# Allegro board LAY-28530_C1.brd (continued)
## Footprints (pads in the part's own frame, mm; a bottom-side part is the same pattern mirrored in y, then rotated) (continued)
FUSE_HOLD_10P4X3_TH
  rect 1.905x1.905 hole 1.295: 1(0,0)
  round 1.905 hole 1.295: 2(5.1,-1.199)
HDR1X3_50MIL
  rect 1.092x1.092 hole 0.711: 1(0,0)
  round 1.092 hole 0.711: 2(0,-1.27) 3(0,-2.54)
HDR2X4_50MIL
  rect 1.092x1.092 hole 0.711: 1(0,0)
  round 1.092 hole 0.711: 2(1.27,0) 3(0,-1.27) 4(1.27,-1.27) 5(0,-2.54) 6(1.27,-2.54) 7(0,-3.81) 8(1.27,-3.81)
HDR102
  rect 1.524x1.524 hole 1.016: 1(0,0)
  round 1.524 hole 1.016: 2(0,-2.54)
HDR103
  rect 1.524x1.524 hole 1.016: 1(0,0)
  round 1.524 hole 1.016: 2(0,-2.54) 3(0,-5.08)
HDR208_HTST_SM
  rect 5.08x1.27 smd: 1(-3.429,8.89) 2(3.429,8.89) 3(-3.429,6.35) 4(3.429,6.35) 5(-3.429,3.81) 6(3.429,3.81) 7(-3.429,1.27) 8(3.429,1.27) 9(-3.429,-1.27) 10(3.429,-1.27) 11(-3.429,-3.81) 12(3.429,-3.81) 13(-3.429,-6.35) 14(3.429,-6.35) 15(-3.429,-8.89) 16(3.429,-8.89)
IND2_4P3SQ_XFL4020
  rect 0.965x3.404 smd: 1(-1.186,0) 2(1.186,0)
IND2_4P3X4P3
  rect 1.118x3.708 smd: 1(-1.501,0) 2(1.501,0)
IND2_XAL40
  rect 0.965x3.708 smd: 1(-1.186,0) 2(1.186,0)
IND2_XAL50XX_222
  rect 1.168x4.394 smd: 1(-1.651,0) 2(1.651,0)
IND4_CHOKE_0805
  rect 0.914x0.406 smd: 1(-0.851,-0.399) 2(0.851,-0.399) 3(0.851,0.399) 4(-0.851,0.399)
IND_0402
  round 0.635 smd: 1(-0.508,0) 2(0.508,0)
IND_0603
  rect 0.991x0.813 smd: 1(-0.691,0) 2(0.691,0)
IND_0805
  rect 1.295x1.499 smd: 1(-0.978,0) 2(0.978,0)
IND_DO1608
  rect 1.397x3.556 smd: 1(-2.743,0) 2(2.743,0)
IND_DO1813
  rect 1.905x4.089 smd: 1(-3.487,0) 2(3.487,0)
IND_DS3316
  rect 2.997x2.794 smd: 1(-5.08,0) 2(5.08,0)
JUMP1X7-6040
  rect 1.524x1.524 hole 1.016: 1(0,0)
  round 1.524 hole 1.016: 2(0,-2.54) 3(0,-5.08) 4(0,-7.62) 5(0,-10.16) 6(0,-12.7) 7(0,-15.24)
LED2_2P54_6P6X4P3MM
  round 1.676 hole 1.067: A(0,2.54)
  rect 1.676x1.676 hole 1.067: C(0,0)
LED4_2P54_9P3X4P5MM
  rect 1.727x1.727 hole 1.092: 1(0,0)
  round 1.727 hole 1.092: 2(-2.54,0) 3(0,-2.54) 4(-2.54,-2.54)
LED_0603
  rect 0.838x0.787 smd: A(-0.775,0) C(0.775,0)
MH175-125P
  round 4.445 hole 3.175: 1(0,0)
MSOP_10_0P5_3X3
  rect 1.372x0.279 smd: 1(-2.24,1.001) 2(-2.24,0.5) 3(-2.24,0) 4(-2.24,-0.5) 5(-2.24,-1.001) 6(2.24,-1.001) 7(2.24,-0.5) 8(2.24,0) 9(2.24,0.5) 10(2.24,1.001)
PQFN16_0P4_2P65X1P85
  rect 0.203x0.762 smd: 1(-0.599,-0.724)
  rect 0.203x0.66 smd: 2(-0.201,-0.775) 3(0.201,-0.775) 4(0.599,-0.775) 9(0.599,0.775) 10(0.201,0.775) 11(-0.201,0.775) 12(-0.599,0.775)
  rect 0.66x0.203 smd: 5(1.209,-0.599) 6(1.209,-0.201) 7(1.209,0.201) 8(1.209,0.599) 13(-1.209,0.599) 14(-1.209,0.201) 15(-1.209,-0.201) 16(-1.209,-0.599)
QFN24_0P5_4X4_EP2P2
  oval 0.813x0.279 smd: 1(-1.859,1.25) 2(-1.859,0.749) 3(-1.859,0.249) 4(-1.859,-0.249) 5(-1.859,-0.749) 6(-1.859,-1.25) 13(1.859,-1.25) 14(1.859,-0.749) 15(1.859,-0.249) 16(1.859,0.249) 17(1.859,0.749) 18(1.859,1.25)
  oval 0.279x0.813 smd: 7(-1.25,-1.859) 8(-0.749,-1.859) 9(-0.249,-1.859) 10(0.249,-1.859) 11(0.749,-1.859) 12(1.25,-1.859) 19(1.25,1.859) 20(0.749,1.859) 21(0.249,1.859) 22(-0.249,1.859) 23(-0.749,1.859) 24(-1.25,1.859)
  rect 2.438x2.438 smd: 25(0,0)
QFN24_4X4MM
  rect 0.279x0.787 smd: 1(-1.25,-1.956) 2(-0.749,-1.956) 3(-0.249,-1.956) 4(0.249,-1.956) 5(0.749,-1.956) 6(1.25,-1.956) 13(1.25,1.956) 14(0.749,1.956) 15(0.249,1.956) 16(-0.249,1.956) 17(-0.749,1.956) 18(-1.25,1.956)
  rect 0.787x0.279 smd: 7(1.956,-1.25) 8(1.956,-0.749) 9(1.956,-0.249) 10(1.956,0.249) 11(1.956,0.749) 12(1.956,1.25) 19(-1.956,1.25) 20(-1.956,0.749) 21(-1.956,0.249) 22(-1.956,-0.249) 23(-1.956,-0.749) 24(-1.956,-1.25)
  rect 2.515x2.515 smd: 25(0,0)
QFN28_3X6_0P5
  rect 0.686x0.254 smd: 1(-1.493,2.25) 2(-1.493,1.75) 3(-1.493,1.25) 4(-1.493,0.749) 5(-1.493,0.249) 6(-1.493,-0.249) 7(-1.493,-0.749) 8(-1.493,-1.25) 9(-1.493,-1.75) 10(-1.493,-2.25) 15(1.493,-2.25) 16(1.493,-1.75) 17(1.493,-1.25) 18(1.493,-0.749) 19(1.493,-0.249) 20(1.493,0.249) 21(1.493,0.749) 22(1.493,1.25) 23(1.493,1.75) 24(1.493,2.25)
  rect 0.254x0.686 smd: 11(-0.749,-2.992) 12(-0.249,-2.992) 13(0.249,-2.992) 14(0.749,-2.992) 25(0.749,2.992) 26(0.249,2.992) 27(-0.249,2.992) 28(-0.749,2.992)
  rect 1.702x4.75 smd: 29(0,0)
QFN56_0P5_8X8_EP4P1X4P4
  oval 0.838x0.279 smd: 1(-3.97,3.251) 14(-3.97,-3.251) 29(3.97,-3.251) 42(3.97,3.251)
  rect 0.838x0.279 smd: 2(-3.97,2.751) 3(-3.97,2.25) 4(-3.97,1.75) 5(-3.97,1.25) 6(-3.97,0.749) 7(-3.97,0.249) 8(-3.97,-0.249) 9(-3.97,-0.749) 10(-3.97,-1.25) 11(-3.97,-1.75) 12(-3.97,-2.25) 13(-3.97,-2.751) 30(3.97,-2.751) 31(3.97,-2.25) 32(3.97,-1.75) 33(3.97,-1.25) 34(3.97,-0.749) 35(3.97,-0.249) 36(3.97,0.249) 37(3.97,0.749) 38(3.97,1.25) 39(3.97,1.75) 40(3.97,2.25) 41(3.97,2.751)
  oval 0.279x0.838 smd: 15(-3.251,-3.97) 28(3.251,-3.97) 43(3.251,3.97) 56(-3.251,3.97)
  rect 0.279x0.838 smd: 16(-2.751,-3.97) 17(-2.25,-3.97) 18(-1.75,-3.97) 19(-1.25,-3.97) 20(-0.749,-3.97) 21(-0.249,-3.97) 22(0.249,-3.97) 23(0.749,-3.97) 24(1.25,-3.97) 25(1.75,-3.97) 26(2.25,-3.97) 27(2.751,-3.97) 44(2.751,3.97) 45(2.25,3.97) 46(1.75,3.97) 47(1.25,3.97) 48(0.749,3.97) 49(0.249,3.97) 50(-0.249,3.97) 51(-0.749,3.97) 52(-1.25,3.97) 53(-1.75,3.97) 54(-2.25,3.97) 55(-2.751,3.97)
  rect 4.115x4.42 smd: 57(0,0)
QFN_48_0P4_6X6MM
  rect 0.838x0.203 smd: 1(-2.936,2.2) 2(-2.936,1.801) 3(-2.936,1.399) 4(-2.936,1.001) 5(-2.936,0.599) 6(-2.936,0.201) 7(-2.936,-0.201) 8(-2.936,-0.599) 9(-2.936,-1.001) 10(-2.936,-1.399) 11(-2.936,-1.801) 12(-2.936,-2.2) 25(2.936,-2.2) 26(2.936,-1.801) 27(2.936,-1.399) 28(2.936,-1.001) 29(2.936,-0.599) 30(2.936,-0.201) 31(2.936,0.201) 32(2.936,0.599) 33(2.936,1.001) 34(2.936,1.399) 35(2.936,1.801) 36(2.936,2.2)
  rect 0.203x0.838 smd: 13(-2.2,-2.936) 14(-1.801,-2.936) 15(-1.399,-2.936) 16(-1.001,-2.936) 17(-0.599,-2.936) 18(-0.201,-2.936) 19(0.201,-2.936) 20(0.599,-2.936) 21(1.001,-2.936) 22(1.399,-2.936) 23(1.801,-2.936) 24(2.2,-2.936) 37(2.2,2.936) 38(1.801,2.936) 39(1.399,2.936) 40(1.001,2.936) 41(0.599,2.936) 42(0.201,2.936) 43(-0.201,2.936) 44(-0.599,2.936) 45(-1.001,2.936) 46(-1.399,2.936) 47(-1.801,2.936) 48(-2.2,2.936)
  rect 4.597x4.597 smd: 49(0,0)
RC0402_25
  round 0.635 smd: 1(-0.508,0) 2(0.508,0)
RC0603_OV
  oval 0.889x1.143 smd: 1(-0.762,0) 2(0.762,0)
RC0805_OV
  oval 0.889x1.524 smd: 1(-0.965,0) 2(0.965,0)
RC1206_OV
  oval 1.016x1.778 smd: 1(-1.524,0) 2(1.524,0)
SKT_BAT_225X886_3V
  rect 1.651x1.651 hole 1.016: 1(0,0)
  round 1.651 hole 1.016: 2(10,0) 3(5.001,3.47)
SKT_BGA525_0P8_58P6SQ_SM
  round 0.254 hole 3.708 unplated: (-24.13,24.13) (-24.13,-24.13) (24.13,24.13) (24.13,-24.13)
  round 0.254 hole 2.438 unplated: (-19.05,24.13) (24.13,-19.05)
  round 0.381 smd: A2(-8.001,8.801) A3(-7.201,8.801) A4(-6.401,8.801) A5(-5.601,8.801) A6(-4.801,8.801) A7(-4,8.801) A8(-3.2,8.801) A9(-2.4,8.801) A10(-1.6,8.801) A11(-0.8,8.801) A12(0,8.801) A13(0.8,8.801) A14(1.6,8.801) A15(2.4,8.801) A16(3.2,8.801) A17(4,8.801) A18(4.801,8.801) A19(5.601,8.801) A20(6.401,8.801) A21(7.201,8.801) A22(8.001,8.801) AA1(-8.801,-7.201) AA2(-8.001,-7.201) AA3(-7.201,-7.201) AA4(-6.401,-7.201) AA5(-5.601,-7.201) AA6(-4.801,-7.201) AA7(-4,-7.201) AA8(-3.2,-7.201) AA9(-2.4,-7.201) AA10(-1.6,-7.201) AA11(-0.8,-7.201) AA12(0,-7.201) AA13(0.8,-7.201) AA14(1.6,-7.201) AA15(2.4,-7.201) AA16(3.2,-7.201) AA17(4,-7.201) AA18(4.801,-7.201) AA19(5.601,-7.201) AA20(6.401,-7.201) AA21(7.201,-7.201) AA22(8.001,-7.201) AA23(8.801,-7.201) AB1(-8.801,-8.001) AB2(-8.001,-8.001) AB3(-7.201,-8.001) AB4(-6.401,-8.001) AB5(-5.601,-8.001) AB6(-4.801,-8.001) AB7(-4,-8.001) AB8(-3.2,-8.001) AB9(-2.4,-8.001) AB10(-1.6,-8.001) AB11(-0.8,-8.001) AB12(0,-8.001) AB13(0.8,-8.001) AB14(1.6,-8.001) AB15(2.4,-8.001) AB16(3.2,-8.001) AB17(4,-8.001) AB18(4.801,-8.001) AB19(5.601,-8.001) AB20(6.401,-8.001) AB21(7.201,-8.001) AB22(8.001,-8.001) AB23(8.801,-8.001) AC2(-8.001,-8.801) AC3(-7.201,-8.801) AC4(-6.401,-8.801) AC5(-5.601,-8.801) AC6(-4.801,-8.801) AC7(-4,-8.801) AC8(-3.2,-8.801) AC9(-2.4,-8.801) AC10(-1.6,-8.801) AC11(-0.8,-8.801) AC12(0,-8.801) AC13(0.8,-8.801) AC14(1.6,-8.801) AC15(2.4,-8.801) AC16(3.2,-8.801) AC17(4,-8.801) AC18(4.801,-8.801) AC19(5.601,-8.801) AC20(6.401,-8.801) AC21(7.201,-8.801) AC22(8.001,-8.801) B1(-8.801,8.001) B2(-8.001,8.001) B3(-7.201,8.001) B4(-6.401,8.001) B5(-5.601,8.001) B6(-4.801,8.001) B7(-4,8.001) B8(-3.2,8.001) B9(-2.4,8.001) B10(-1.6,8.001) B11(-0.8,8.001) B12(0,8.001) B13(0.8,8.001) B14(1.6,8.001) B15(2.4,8.001) B16(3.2,8.001) B17(4,8.001) B18(4.801,8.001) B19(5.601,8.001) B20(6.401,8.001) B21(7.201,8.001) B22(8.001,8.001) B23(8.801,8.001) C1(-8.801,7.201) C2(-8.001,7.201) C3(-7.201,7.201) C4(-6.401,7.201) C5(-5.601,7.201) C6(-4.801,7.201) C7(-4,7.201) C8(-3.2,7.201) C9(-2.4,7.201) C10(-1.6,7.201) C11(-0.8,7.201) C12(0,7.201) C13(0.8,7.201) C14(1.6,7.201) C15(2.4,7.201) C16(3.2,7.201) C17(4,7.201) C18(4.801,7.201) C19(5.601,7.201) C20(6.401,7.201) C21(7.201,7.201) C22(8.001,7.201) C23(8.801,7.201) D1(-8.801,6.401) D2(-8.001,6.401) D3(-7.201,6.401) D4(-6.401,6.401) D5(-5.601,6.401) D6(-4.801,6.401) D7(-4,6.401) D8(-3.2,6.401) D9(-2.4,6.401) D10(-1.6,6.401) D11(-0.8,6.401) D12(0,6.401) D13(0.8,6.401) D14(1.6,6.401) D15(2.4,6.401) D16(3.2,6.401) D17(4,6.401) D18(4.801,6.401) D19(5.601,6.401) D20(6.401,6.401) D21(7.201,6.401) D22(8.001,6.401) D23(8.801,6.401) E1(-8.801,5.601) E2(-8.001,5.601) E3(-7.201,5.601) E4(-6.401,5.601) E5(-5.601,5.601) E6(-4.801,5.601) E7(-4,5.601) E8(-3.2,5.601) E9(-2.4,5.601) E10(-1.6,5.601) E11(-0.8,5.601) E12(0,5.601) E13(0.8,5.601) E14(1.6,5.601) E15(2.4,5.601) E16(3.2,5.601) E17(4,5.601) E18(4.801,5.601) E19(5.601,5.601) E20(6.401,5.601) E21(7.201,5.601) E22(8.001,5.601) E23(8.801,5.601) F1(-8.801,4.801) F2(-8.001,4.801) F3(-7.201,4.801) F4(-6.401,4.801) F5(-5.601,4.801) F6(-4.801,4.801) F7(-4,4.801) F8(-3.2,4.801) F9(-2.4,4.801) F10(-1.6,4.801) F11(-0.8,4.801) F12(0,4.801) F13(0.8,4.801) F14(1.6,4.801) F15(2.4,4.801) F16(3.2,4.801) F17(4,4.801) F18(4.801,4.801) F19(5.601,4.801) F20(6.401,4.801) F21(7.201,4.801) F22(8.001,4.801) F23(8.801,4.801) G1(-8.801,4) G2(-8.001,4) G3(-7.201,4) G4(-6.401,4) G5(-5.601,4) G6(-4.801,4) G7(-4,4) G8(-3.2,4) G9(-2.4,4) G10(-1.6,4) G11(-0.8,4) G12(0,4) G13(0.8,4) G14(1.6,4) G15(2.4,4) G16(3.2,4) G17(4,4) G18(4.801,4) G19(5.601,4) G20(6.401,4) G21(7.201,4) G22(8.001,4) G23(8.801,4) H1(-8.801,3.2) H2(-8.001,3.2) H3(-7.201,3.2) H4(-6.401,3.2) H5(-5.601,3.2) H6(-4.801,3.2) H7(-4,3.2) H8(-3.2,3.2) H9(-2.4,3.2) H10(-1.6,3.2) H11(-0.8,3.2) H12(0,3.2) H13(0.8,3.2) H14(1.6,3.2) H15(2.4,3.2) H16(3.2,3.2) H17(4,3.2) H18(4.801,3.2) H19(5.601,3.2) H20(6.401,3.2) H21(7.201,3.2) H22(8.001,3.2) H23(8.801,3.2) J1(-8.801,2.4) J2(-8.001,2.4) J3(-7.201,2.4) J4(-6.401,2.4) J5(-5.601,2.4) J6(-4.801,2.4) J7(-4,2.4) J8(-3.2,2.4) J9(-2.4,2.4) J10(-1.6,2.4) J11(-0.8,2.4) J12(0,2.4) J13(0.8,2.4) J14(1.6,2.4) J15(2.4,2.4) J16(3.2,2.4) J17(4,2.4) J18(4.801,2.4) J19(5.601,2.4) J20(6.401,2.4) J21(7.201,2.4) J22(8.001,2.4) J23(8.801,2.4) K1(-8.801,1.6) K2(-8.001,1.6) K3(-7.201,1.6) K4(-6.401,1.6) K5(-5.601,1.6) K6(-4.801,1.6) K7(-4,1.6) K8(-3.2,1.6) K9(-2.4,1.6) K10(-1.6,1.6) K11(-0.8,1.6) K12(0,1.6) K13(0.8,1.6) K14(1.6,1.6) K15(2.4,1.6) K16(3.2,1.6) K17(4,1.6) K18(4.801,1.6) K19(5.601,1.6) K20(6.401,1.6) K21(7.201,1.6) K22(8.001,1.6) K23(8.801,1.6) L1(-8.801,0.8) L2(-8.001,0.8) L3(-7.201,0.8) L4(-6.401,0.8) L5(-5.601,0.8) L6(-4.801,0.8) L7(-4,0.8) L8(-3.2,0.8) L9(-2.4,0.8) L10(-1.6,0.8) L11(-0.8,0.8) L12(0,0.8) L13(0.8,0.8) L14(1.6,0.8) L15(2.4,0.8) L16(3.2,0.8) L17(4,0.8) L18(4.801,0.8) L19(5.601,0.8) L20(6.401,0.8) L21(7.201,0.8) L22(8.001,0.8) L23(8.801,0.8) M1(-8.801,0) M2(-8.001,0) M3(-7.201,0) M4(-6.401,0) M5(-5.601,0) M6(-4.801,0) M7(-4,0) M8(-3.2,0) M9(-2.4,0) M10(-1.6,0) M11(-0.8,0) M12(0,0) M13(0.8,0) M14(1.6,0) M15(2.4,0) M16(3.2,0) M17(4,0) M18(4.801,0) M19(5.601,0) M20(6.401,0) M21(7.201,0) M22(8.001,0) M23(8.801,0) N1(-8.801,-0.8) N2(-8.001,-0.8) N3(-7.201,-0.8) N4(-6.401,-0.8) N5(-5.601,-0.8) N6(-4.801,-0.8) N7(-4,-0.8) N8(-3.2,-0.8) N9(-2.4,-0.8) N10(-1.6,-0.8) N11(-0.8,-0.8) N12(0,-0.8) N13(0.8,-0.8) N14(1.6,-0.8) N15(2.4,-0.8) N16(3.2,-0.8) N17(4,-0.8) N18(4.801,-0.8) N19(5.601,-0.8) N20(6.401,-0.8) N21(7.201,-0.8) N22(8.001,-0.8) N23(8.801,-0.8) P1(-8.801,-1.6) P2(-8.001,-1.6) P3(-7.201,-1.6) P4(-6.401,-1.6) P5(-5.601,-1.6) P6(-4.801,-1.6) P7(-4,-1.6) P8(-3.2,-1.6) P9(-2.4,-1.6) P10(-1.6,-1.6) P11(-0.8,-1.6) P12(0,-1.6) P13(0.8,-1.6) P14(1.6,-1.6) P15(2.4,-1.6) P16(3.2,-1.6) P17(4,-1.6) P18(4.801,-1.6) P19(5.601,-1.6) P20(6.401,-1.6) P21(7.201,-1.6) P22(8.001,-1.6) P23(8.801,-1.6) R1(-8.801,-2.4) R2(-8.001,-2.4) R3(-7.201,-2.4) R4(-6.401,-2.4) R5(-5.601,-2.4) R6(-4.801,-2.4) R7(-4,-2.4) R8(-3.2,-2.4) R9(-2.4,-2.4) R10(-1.6,-2.4) R11(-0.8,-2.4) R12(0,-2.4) R13(0.8,-2.4) R14(1.6,-2.4) R15(2.4,-2.4) R16(3.2,-2.4) R17(4,-2.4) R18(4.801,-2.4) R19(5.601,-2.4) R20(6.401,-2.4) R21(7.201,-2.4) R22(8.001,-2.4) R23(8.801,-2.4) T1(-8.801,-3.2) T2(-8.001,-3.2) T3(-7.201,-3.2) T4(-6.401,-3.2) T5(-5.601,-3.2) T6(-4.801,-3.2) T7(-4,-3.2) T8(-3.2,-3.2) T9(-2.4,-3.2) T10(-1.6,-3.2) T11(-0.8,-3.2) T12(0,-3.2) T13(0.8,-3.2) T14(1.6,-3.2) T15(2.4,-3.2) T16(3.2,-3.2) T17(4,-3.2) T18(4.801,-3.2) T19(5.601,-3.2) T20(6.401,-3.2) T21(7.201,-3.2) T22(8.001,-3.2) T23(8.801,-3.2) U1(-8.801,-4) U2(-8.001,-4) U3(-7.201,-4) U4(-6.401,-4) U5(-5.601,-4) U6(-4.801,-4) U7(-4,-4) U8(-3.2,-4) U9(-2.4,-4) U10(-1.6,-4) U11(-0.8,-4) U12(0,-4) U13(0.8,-4) U14(1.6,-4) U15(2.4,-4) U16(3.2,-4) U17(4,-4) U18(4.801,-4) U19(5.601,-4) U20(6.401,-4) U21(7.201,-4) U22(8.001,-4) U23(8.801,-4) V1(-8.801,-4.801) V2(-8.001,-4.801) V3(-7.201,-4.801) V4(-6.401,-4.801) V5(-5.601,-4.801) V6(-4.801,-4.801) V7(-4,-4.801) V8(-3.2,-4.801) V9(-2.4,-4.801) V10(-1.6,-4.801) V11(-0.8,-4.801) V12(0,-4.801) V13(0.8,-4.801) V14(1.6,-4.801) V15(2.4,-4.801) V16(3.2,-4.801) V17(4,-4.801) V18(4.801,-4.801) V19(5.601,-4.801) V20(6.401,-4.801) V21(7.201,-4.801) V22(8.001,-4.801) V23(8.801,-4.801) W1(-8.801,-5.601) W2(-8.001,-5.601) W3(-7.201,-5.601) W4(-6.401,-5.601) W5(-5.601,-5.601) W6(-4.801,-5.601) W7(-4,-5.601) W8(-3.2,-5.601) W9(-2.4,-5.601) W10(-1.6,-5.601) W11(-0.8,-5.601) W12(0,-5.601) W13(0.8,-5.601) W14(1.6,-5.601) W15(2.4,-5.601) W16(3.2,-5.601) W17(4,-5.601) W18(4.801,-5.601) W19(5.601,-5.601) W20(6.401,-5.601) W21(7.201,-5.601) W22(8.001,-5.601) W23(8.801,-5.601) Y1(-8.801,-6.401) Y2(-8.001,-6.401) Y3(-7.201,-6.401) Y4(-6.401,-6.401) Y5(-5.601,-6.401) Y6(-4.801,-6.401) Y7(-4,-6.401) Y8(-3.2,-6.401) Y9(-2.4,-6.401) Y10(-1.6,-6.401) Y11(-0.8,-6.401) Y12(0,-6.401) Y13(0.8,-6.401) Y14(1.6,-6.401) Y15(2.4,-6.401) Y16(3.2,-6.401) Y17(4,-6.401) Y18(4.801,-6.401) Y19(5.601,-6.401) Y20(6.401,-6.401) Y21(7.201,-6.401) Y22(8.001,-6.401) Y23(8.801,-6.401)
SLP2710P8
  rect 0.691x0.221 smd: 1(-0.437,1.1) 2(-0.437,0.599) 3(-0.437,-0.599) 4(-0.437,-1.1) 5(0.437,-1.1) 6(0.437,-0.599) 7(0.437,0.599) 8(0.437,1.1)
  rect 1.549x0.399 smd: 9(0,0)
SMA
  rect 2.032x2.032 smd: A(1.905,0) C(-1.905,0)
SMA2_4_4P6X2P9
  rect 2.515x1.702 smd: A(1.999,0) C(-1.999,0)
SO8
  rect 2.032x0.635 smd: 1(-2.794,1.905) 2(-2.794,0.635) 3(-2.794,-0.635) 4(-2.794,-1.905) 5(2.794,-1.905) 6(2.794,-0.635) 7(2.794,0.635) 8(2.794,1.905)
SO8_1P27_4X5
  rect 1.6x0.61 smd: 1(-2.7,1.905) 2(-2.7,0.635) 3(-2.7,-0.635) 4(-2.7,-1.905) 5(2.7,-1.905) 6(2.7,-0.635) 7(2.7,0.635) 8(2.7,1.905)
SOD123
  rect 1.016x1.27 smd: A(1.651,0) C(-1.651,0)
SOD123_A
  rect 0.914x1.219 smd: A(1.699,0) C(-1.699,0)
SOD323
  rect 0.889x1.219 smd: A(0,1.27) C(0,-1.27)
SOD-123
  rect 1.321x1.219 smd: A(-1.626,0) C(1.626,0)
SOIC16_1P27_7P5X10P3
  rect 1.803x0.61 smd: 1(-4.641,4.445) 2(-4.641,3.175) 3(-4.641,1.905) 4(-4.641,0.635) 5(-4.641,-0.635) 6(-4.641,-1.905) 7(-4.641,-3.175) 8(-4.641,-4.445) 9(4.641,-4.445) 10(4.641,-3.175) 11(4.641,-1.905) 12(4.641,-0.635) 13(4.641,0.635) 14(4.641,1.905) 15(4.641,3.175) 16(4.641,4.445)
SOT23
  rect 0.762x1.219 smd: 1(-1.016,-1.092) 2(1.016,-1.092) 3(0,1.092)
SOT23-40X40
  rect 1.016x1.016 smd: 1(-0.94,-1.003) 2(0.94,-1.003) 3(0,1.003)
SOT23_S6
  rect 1.27x0.635 smd: 1(-1.219,0.94) 2(-1.219,0) 3(-1.219,-0.94) 4(1.219,-0.94) 5(1.219,0) 6(1.219,0.94)
SOT143-25X60
  rect 1.524x1.016 smd: 1(0.965,-0.749)
  rect 1.524x0.635 smd: 2(0.965,0.953) 3(-0.965,0.953) 4(-0.965,-0.953)
SOT-23-5
  rect 0.686x0.991 smd: 1(-0.953,-1.295) 2(0,-1.295) 3(0.953,-1.295) 4(0.953,1.295) 5(-0.953,1.295)
SSOP16
  rect 2.032x0.406 smd: 1(-3.48,2.276) 2(-3.48,1.626) 3(-3.48,0.975) 4(-3.48,0.325) 5(-3.48,-0.325) 6(-3.48,-0.975) 7(-3.48,-1.626) 8(-3.48,-2.276) 9(3.48,-2.276) 10(3.48,-1.626) 11(3.48,-0.975) 12(3.48,-0.325) 13(3.48,0.325) 14(3.48,0.975) 15(3.48,1.626) 16(3.48,2.276)
SW_4P_7P1X15P8
  rect 1.651x1.651 hole 0.991: 1(0,0)
  round 1.651 hole 0.991: 2(4.501,0)
  round 2.159 hole 1.295: 3(-1.25,2.499) 4(5.751,2.499)
SW_DIP16_8POS_SM
  rect 0.762x1.27 smd: 1(-4.45,-3.81) 2(-3.18,-3.81) 3(-1.91,-3.81) 4(-0.64,-3.81) 5(0.64,-3.81) 6(1.91,-3.81) 7(3.18,-3.81) 8(4.45,-3.81) 9(4.45,3.81) 10(3.18,3.81) 11(1.91,3.81) 12(0.64,3.81) 13(-0.64,3.81) 14(-1.91,3.81) 15(-3.18,3.81) 16(-4.45,3.81)
TDFN10_0P5_3P1X3P1
  rect 0.762x0.254 smd: 1(-1.481,1.001) 2(-1.481,0.5) 3(-1.481,0) 4(-1.481,-0.5) 5(-1.481,-1.001) 6(1.481,-1.001) 7(1.481,-0.5) 8(1.481,0) 9(1.481,0.5) 10(1.481,1.001)
  rect 1.6x2.413 smd: 11(0,0)
TESTPOINT_35MIL
  round 0.889 smd: 1(0,0)
TO252AA
  rect 1.6x2.997 smd: 1(-2.286,-4.006) 3(2.286,-4.006)
  rect 6.096x6.604 smd: 4(0,2.306)
TSOP56_0P5_18_4X14_IN
  rect 1.27x0.305 smd: 1(-9.85,6.749) 2(-9.85,6.251) 3(-9.85,5.751) 4(-9.85,5.25) 5(-9.85,4.75) 6(-9.85,4.249) 7(-9.85,3.749) 8(-9.85,3.249) 9(-9.85,2.751) 10(-9.85,2.25) 11(-9.85,1.75) 12(-9.85,1.25) 13(-9.85,0.749) 14(-9.85,0.249) 15(-9.85,-0.249) 16(-9.85,-0.749) 17(-9.85,-1.25) 18(-9.85,-1.75) 19(-9.85,-2.25) 20(-9.85,-2.751) 21(-9.85,-3.249) 22(-9.85,-3.749) 23(-9.85,-4.249) 24(-9.85,-4.75) 25(-9.85,-5.25) 26(-9.85,-5.751) 27(-9.85,-6.251) 28(-9.85,-6.749) 29(9.85,-6.749) 30(9.85,-6.251) 31(9.85,-5.751) 32(9.85,-5.25) 33(9.85,-4.75) 34(9.85,-4.249) 35(9.85,-3.749) 36(9.85,-3.249) 37(9.85,-2.751) 38(9.85,-2.25) 39(9.85,-1.75) 40(9.85,-1.25) 41(9.85,-0.749) 42(9.85,-0.249) 43(9.85,0.249) 44(9.85,0.749) 45(9.85,1.25) 46(9.85,1.75) 47(9.85,2.25) 48(9.85,2.751) 49(9.85,3.249) 50(9.85,3.749) 51(9.85,4.249) 52(9.85,4.75) 53(9.85,5.25) 54(9.85,5.751) 55(9.85,6.251) 56(9.85,6.749)
TSSOP8
  rect 1.778x0.356 smd: 1(-2.819,0.975) 2(-2.819,0.325) 3(-2.819,-0.325) 4(-2.819,-0.975) 5(2.819,-0.975) 6(2.819,-0.325) 7(2.819,0.325) 8(2.819,0.975)
TSSOP16
  rect 1.524x0.305 smd: 1(-3.048,2.276) 2(-3.048,1.626) 3(-3.048,0.975) 4(-3.048,0.325) 5(-3.048,-0.325) 6(-3.048,-0.975) 7(-3.048,-1.626) 8(-3.048,-2.276) 9(3.048,-2.276) 10(3.048,-1.626) 11(3.048,-0.975) 12(3.048,-0.325) 13(3.048,0.325) 14(3.048,0.975) 15(3.048,1.626) 16(3.048,2.276)
TSSOP48-11X70
  oval 0.279x1.778 smd: 1(-5.748,-3.759) 2(-5.248,-3.759) 3(-4.75,-3.759) 4(-4.249,-3.759) 5(-3.749,-3.759) 6(-3.249,-3.759) 7(-2.748,-3.759) 8(-2.25,-3.759) 9(-1.75,-3.759) 10(-1.25,-3.759) 11(-0.749,-3.759) 12(-0.249,-3.759) 13(0.249,-3.759) 14(0.749,-3.759) 15(1.25,-3.759) 16(1.75,-3.759) 17(2.25,-3.759) 18(2.748,-3.759) 19(3.249,-3.759) 20(3.749,-3.759) 21(4.249,-3.759) 22(4.75,-3.759) 23(5.248,-3.759) 24(5.748,-3.759) 25(5.748,3.759) 26(5.248,3.759) 27(4.75,3.759) 28(4.249,3.759) 29(3.749,3.759) 30(3.249,3.759) 31(2.748,3.759) 32(2.25,3.759) 33(1.75,3.759) 34(1.25,3.759) 35(0.749,3.759) 36(0.249,3.759) 37(-0.249,3.759) 38(-0.749,3.759) 39(-1.25,3.759) 40(-1.75,3.759) 41(-2.25,3.759) 42(-2.748,3.759) 43(-3.249,3.759) 44(-3.749,3.759) 45(-4.249,3.759) 46(-4.75,3.759) 47(-5.248,3.759) 48(-5.748,3.759)
unnamed#2
  round 1.524 smd: (0,0)
USB_A_TH_SAMTEC
  rect 1.676x1.676 hole 1.016: A1(0,0)
  round 1.676 hole 1.016: A2(2.499,0) A3(4.501,0) A4(7,0)
  oval 1.702x2.997 hole 1.194x2.489: S1(-3.071,-2.731) S2(10.071,-2.731)
USOP-8
  rect 1.016x0.406 smd: 1(-2.202,0.975) 2(-2.202,0.325) 3(-2.202,-0.325) 4(-2.202,-0.975) 5(2.202,-0.975) 6(2.202,-0.325) 7(2.202,0.325) 8(2.202,0.975)
VFBGA63_0P8_9X11
  round 0.356 smd: A1(-3.599,4.399) A2(-2.799,4.399) A9(2.799,4.399) A10(3.599,4.399) B1(-3.599,3.599) B9(2.799,3.599) B10(3.599,3.599) C3(-1.999,2.799) C4(-1.199,2.799) C5(-0.399,2.799) C6(0.399,2.799) C7(1.199,2.799) C8(1.999,2.799) D3(-1.999,1.999) D4(-1.199,1.999) D5(-0.399,1.999) D6(0.399,1.999) D7(1.199,1.999) D8(1.999,1.999) E3(-1.999,1.199) E4(-1.199,1.199) E5(-0.399,1.199) E6(0.399,1.199) E7(1.199,1.199) E8(1.999,1.199) F3(-1.999,0.399) F4(-1.199,0.399) F5(-0.399,0.399) F6(0.399,0.399) F7(1.199,0.399) F8(1.999,0.399) G3(-1.999,-0.399) G4(-1.199,-0.399) G5(-0.399,-0.399) G6(0.399,-0.399) G7(1.199,-0.399) G8(1.999,-0.399) H3(-1.999,-1.199) H4(-1.199,-1.199) H5(-0.399,-1.199) H6(0.399,-1.199) H7(1.199,-1.199) H8(1.999,-1.199) J3(-1.999,-1.999) J4(-1.199,-1.999) J5(-0.399,-1.999) J6(0.399,-1.999) J7(1.199,-1.999) J8(1.999,-1.999) K3(-1.999,-2.799) K4(-1.199,-2.799) K5(-0.399,-2.799) K6(0.399,-2.799) K7(1.199,-2.799) K8(1.999,-2.799) L1(-3.599,-3.599) L2(-2.799,-3.599) L9(2.799,-3.599) L10(3.599,-3.599) M1(-3.599,-4.399) M2(-2.799,-4.399) M9(2.799,-4.399) M10(3.599,-4.399)
XFMR6_2P54_SM
  rect 1.143x2.032 smd: 1(-3.365,2.54) 2(-3.365,0) 3(-3.365,-2.54) 4(3.365,-2.54) 5(3.365,0) 6(3.365,2.54)
XFMR10_2P5_13X14_SM
  rect 2.54x1.219 smd: 1(7.95,5.001) 2(7.95,2.499) 3(7.95,0) 4(7.95,-2.499) 5(7.95,-5.001) 6(-7.95,-5.001) 7(-7.95,-2.499) 8(-7.95,0) 9(-7.95,2.499) 10(-7.95,5.001)
XTAL4_3P3X2P6_SM_FL
  rect 1.499x1.194 smd: 1(-1.059,-0.8) 2(1.059,-0.8) 3(1.059,0.8) 4(-1.059,0.8)
XTL2_TF_SM
  rect 2.54x1.016 smd: 1(3.749,1.27) 2(3.749,-1.27)
XTLOSC4_3P2X2P5MM_SM
  rect 1.397x1.194 smd: 1(-1.1,-0.8) 2(1.1,-0.8) 3(1.1,0.8) 4(-1.1,0.8)

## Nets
1V2_RST_N: Q15.3(COLLECTOR) R200.2 R201.1 U34.L1(R\E\S\E\T\) U35.L1(R\E\S\E\T\) U36.L1(R\E\S\E\T\) U37.L1(R\E\S\E\T\)
1V8_RST_N: Q14.3(COLLECTOR) R197.2 U14.3(R\E\S\E\T\/RFU) U20.14(R\E\S\E\T\)
12V: C29.1 C39.1 C72.1 C73.1 C74.1 C91.1 C92.1 C96.1 C99.1 C100.2 C101.1 C102.1 C104.2 C282.1 C408.2 C635.1 C636.1 C637.2 C654.1 C655.1 C656.2 J9.2 J18.3 J20.3 J21.3 J23.1 J26.1 R91.1 R100.2 R146.1 R241.1 R242.1 R446.1 U7.8(VIN) U9.17(PVIN1) U9.18(PVIN2) U22.5(VIN1) U22.6(VIN2) U22.7(VIN3) U28.5(VIN1) U28.6(VIN2) U28.7(VIN3) U29.5(VIN1) U29.6(VIN2) U29.7(VIN3) U45.5(VIN1) U45.6(VIN2) U45.7(VIN3) U49.5(VIN1) U49.6(VIN2) U49.7(VIN3)
12V_DECT: C9.1 D6.C(CATHODE) D9.A F1.2 J18.1 J19.1 J20.1 J21.1 J23.3 J26.3 Q6.4(D2) R231.1 R232.2 R247.1
12V_SUP: D9.C D10.C R97.2 R236.2
AVDD_CGA1: C153.1 C154.1 C155.1 C287.1 C290.1 C296.1 C297.1 C298.1 C299.1 C301.1 C310.1 C311.1 C312.1 C317.1 C348.1 C350.1 C352.1 C353.1 C354.1 C385.1 C392.1 C407.1 C424.1 C431.1 C444.1 C461.1 C466.1 C647.1 J10.2 J11.1 L24.1 L29.2 Q21.3(S2) R16.1 R17.1 R135.1 R138.1 R140.1 R142.1 R143.2 R144.2 R150.1 R153.1 R154.1 R155.2 R156.2 R163.1 R165.1 R193.1 R194.2 R197.1 R237.2 R238.2 R239.2 R243.2 R245.1 R251.1 R253.1 R255.1 R257.1 R262.1 R268.1 R272.1 R273.1 R274.1 R276.1 R277.2 R279.1 R281.1 R283.1 R289.1 R290.2 R292.2 R299.2 R301.2 R302.2 R304.2 R308.2 R310.1 R312.2 R314.2 R317.2 R319.2 R321.1 R323.1 R324.1 R325.2 R328.1 R331.1 R356.1 R367.1 R368.1 R420.2 R421.2 R422.2 R423.1 R424.1 R460.1 R461.2 R467.2 R468.2 U14.14(VIO/RFU) U16.D3(VCC1) U16.G4(VCC2) U16.H8(VCC3) U16.J6(VCC4) U20.29(VIO) U21.H11(OVDD1) U21.H12(OVDD2) U21.H13(OVDD3) U21.H14(OVDD4) U21.H15(OVDD5) U21.J8(TH_VDD) U21.L8(CVDD) U21.P8(LVDD1) U21.R8(LVDD2) U21.T8(LVDD3) U23.5(VCC) U24.5(VCC) U25.7(VCC1) U25.18(VCC2) U25.31(VCC3) U25.42(VCC4) U27.5(VCC) U38.25(FB2) U44.13(VCCB) U48.16(VCCP)
AVDD_SD1_PLL1: C590.1 FL2.3(OUT_IN) R294.2 R329.2 R330.2 U38.18(LDO1)
GND: BH1.1 BH2.1 BH3.1 BH4.1 BT1.3(NEG) C3.2 C5.2 C6.2 C7.1 C9.2 C10.2 C11.2 C12.2 C13.2 C14.2 C15.2 C16.2 C17.2 C18.2 C19.1 C20.2 C21.2 C22.2 C23.2 C24.2 C25.2 C26.2 C27.2 C28.2 C29.2 C31.2 C32.1 C33.2 C34.2 C35.2 C36.2 C38.2 C39.2 C40.2 C41.2 C42.2 C43.1 C44.2 C45.2 C46.2 C47.2 C48.2 C49.2 C50.1 C51.1 C52.2 C53.2 C54.2 C55.2 C58.2 C59.2 C60.2 C62.2 C63.2 C64.2 C65.2 C66.2 C67.2 C68.2 C69.2 C70.2 C71.2 C72.2 C73.2 C74.2 C76.2 C77.2 C78.2 C79.2 C80.2 C81.2 C82.2 C84.1 C85.2 C86.2 C88.2 C89.2 C90.2 C91.2 C92.2 C93.2 C94.2 C95.2 C96.2 C97.2 C98.2 C99.2 C100.1 C101.2 C102.2 C103.2 C104.1 C105.2 C107.2 C108.2 C110.2 C111.2 C112.2 C113.2 C114.2 C115.2 C116.2 C117.2 C118.2 C119.2 C120.2 C121.2 C122.2 C123.2 C124.2 C125.2 C126.2 C127.2 C128.2 C129.2 C130.2 C131.2 C132.2 C133.2 C134.2 C135.2 C136.2 C137.2 C138.2 C139.2 C140.2 C141.2 C142.1 C143.2 C144.2 C146.2 C147.2 C148.2 C149.2 C150.2 C151.2 C152.2 C153.2 C154.2 C155.2 C156.2 C157.2 C158.2 C159.2 C160.2 C161.2 C162.2 C163.1 C164.2 C165.2 C166.2 C167.1 C168.1 C169.1 C171.1 C172.1 C176.1 C179.1 C180.2 C182.1 C185.2 C187.1 C189.2 C190.2 C191.1 C192.1 C193.1 C194.1 C195.1 C196.1 C197.1 C198.2 C199.1 C200.1 C201.1 C202.1 C203.1 C204.1 C205.1 C206.1 C207.1 C209.1 C210.1 C211.1 C212.1 C213.1 C214.1 C215.1 C216.1 C218.1 C219.1 C220.1 C221.1 C222.1 C223.1 C224.1 C225.1 C226.1 C227.1 C228.1 C229.2 C230.1 C231.1 C232.1 C233.2 C234.1 C235.1 C236.1 C237.1 C238.1 C239.1 C240.1 C241.2 C242.1 C243.1 C244.1 C245.1 C246.1 C247.2 C248.1 C249.1 C250.2 C251.2 C252.1 C253.1 C254.1 C255.1 C256.1 C257.1 C258.1 C259.1 C260.1 C261.1 C262.1 C263.1 C264.1 C265.1 C266.1 C267.1 C268.1 C269.2 C270.1 C271.1 C272.1 C273.2 C274.2 C275.2 C276.1 C277.2 C278.2 C279.1 C280.1 C281.2 C282.2 C283.2 C284.2 C285.2 C286.2 C287.2 C288.1 C289.1 C290.2 C292.2 C293.2 C294.2 C295.2 C296.2 C297.2 C298.2 C299.2 C300.2 C301.2 C302.2 C303.2 C304.2 C305.2 C306.2 C307.2 C308.2 C309.2 C310.2 C311.2 C312.2 C313.2 C314.2 C315.2 C316.2 C317.2 C318.2 C319.2 C320.2 C321.2 C322.2 C324.2 C325.2 C326.2 C327.2 C331.2 C332.2 C333.2 C334.2 C335.1 C336.1 C337.2 C338.2 C339.2 C340.2 C341.2 C342.2 C343.2 C345.2 C346.2 C347.2 C348.2 C349.2 C350.2 C351.2 C352.2 C353.2 C354.2 C356.1 C357.1 C358.2 C359.2 C360.2 C361.2 C362.2 C363.2 C364.2 C367.2 C368.2 C369.2 C370.2 C371.2 C372.2 C373.2 C374.2 C375.2 C376.2 C378.2 C379.2 C380.2 C382.2 C383.2 C384.2 C385.2 C386.1 C387.2 C388.2 C389.2 C390.2 C392.2 C393.2 C394.2 C395.2 C396.2 C397.2 C398.2 C399.2 C400.2 C401.1 C402.1 C404.2 C406.2 C407.2 C408.1 C410.2 C412.2 C413.2 C414.2 C415.2 C416.2 C418.2 C419.2 C420.2 C422.1 C423.1 C424.2 C425.2 C426.2 C428.2 C430.2 C431.2 C432.2 C433.2 C434.2 C435.2 C436.2 C437.2 C438.2 C439.2 C440.2 C441.2 C442.2 C443.2 C444.2 C445.2 C446.2 C447.2 C449.2 C450.2 C451.1 C452.1 C453.2 C454.2 C455.2 C456.2 C457.2 C458.2 C459.2 C460.2 C461.2 C462.2 C463.2 C466.2 C468.2 C469.2 C470.2 C471.2 C472.2 C473.2 C475.2 C476.2 C477.2 C478.2 C479.2 C480.2 C482.2 C483.2 C484.2 C485.2 C486.2 C487.2 C488.2 C489.2 C490.2 C491.2 C492.2 C493.2 C494.2 C495.2 C496.2 C497.2 C498.2 C499.2 C500.2 C501.2 C502.2 C503.2 C504.2 C505.2 C506.2 C507.2 C508.2 C509.2 C510.2 C511.2 C512.2 C513.2 C514.2 C515.2 C516.2 C517.2 C518.2 C519.2 C520.2 C521.2 C522.2 C523.2 C524.2 C525.2 C526.2 C527.2 C528.2 C529.2 C530.2 C531.2 C532.2 C533.2 C534.2 C536.2 C537.2 C538.2 C539.2 C540.2 C541.2 C542.2 C543.2 C544.2 C545.2 C546.2 C547.2 C548.2 C549.2 C550.2 C551.2 C552.2 C553.2 C554.2 C555.2 C556.2 C557.2 C558.2 C559.2 C560.2 C561.2 C562.2 C563.2 C564.2 C565.2 C566.2 C567.2 C568.2 C569.2 C570.2 C571.2 C572.2 C573.2 C574.2 C575.2 C576.2 C577.2 C578.2 C579.2 C580.2 C581.2 C582.2 C583.2 C590.2 C592.2 C593.2 C594.2 C595.2 C596.2 C597.2 C598.2 C599.2 C600.2 C601.2 C602.2 C603.2 C604.2 C605.2 C606.2 C607.2 C608.2 C609.2 C611.2 C622.2 C623.2 C624.2 C626.2 C627.2 C628.2 C630.2 C631.2 C634.2 C635.2 C636.2 C637.1 C638.2 C639.2 C643.2 C646.2 C647.2 C648.2 C649.2 C650.2 C653.2 C654.2 C655.2 C656.1 C657.2 C658.2 D6.A(ANODE) D11.C(CATHODE) D12.3(CATHODE2) D13.3(CATHODE2) D25.1(ANODE) FL1.2(GND) FL2.2(GND) J1.2 J4.19 J5.19 J6.2 J7.7 J8.2 J9.1 J9.3 J12.2 J13.12 J13.16 J14.2 J16.3(GND1) J16.6(GND2) J16.11(P_GND1) J16.12(P_GND2) L2.1 P1.4 P1.5 P2.4(GND7) P2.9(GND1) P2.15(GND2) P2.18(GND8) P2.21(GND3) P2.26(GND9) P2.27(GND4) P2.29(GND5) P2.34(GND10) P2.35(GND6) P2.40(GND11) P2.50(GND12) P3.4(GND7) P3.9(GND1) P3.15(GND2) P3.18(GND8) P3.21(GND3) P3.26(GND9) P3.27(GND4) P3.29(GND5) P3.34(GND10) P3.35(GND6) P3.40(GND11) P3.50(GND12) Q3.1(SOURCE_1) Q3.2(SOURCE_2) Q3.3(SOURCE_3) Q16.2(EMITTER) Q17.3(C) Q19.1(S2) Q19.3(S2) Q20.2(EMITTER) Q22.1(S2) Q22.3(S2) Q28.2(EMITTER) R5.2 R6.2 R7.2 R10.2 R19.2 R20.1 R21.2 R25.2 R28.1 R29.1 R30.1 R38.2 R44.1 R51.1 R60.1 R63.1 R68.1 R72.1 R73.1 R78.2 R81.2 R87.2 R88.2 R89.1 R90.2 R94.1 R95.2 R98.2 R101.2 R104.1 R107.2 R109.2 R111.2 R114.2 R115.2 R117.2 R122.2 R126.2 R128.2 R129.2 R130.1 R131.1 R132.2 R133.2 R134.2 R136.2 R139.2 R141.2 R147.1 R148.2 R151.2 R202.2 R203.2 R204.1 R205.2 R206.2 R207.1 R210.1 R211.2 R213.1 R214.1 R215.2 R219.2 R230.2 R233.1 R234.2 R240.1 R244.1 R248.1 R249.2 R250.1 R252.1 R254.1 R256.1 R258.1 R261.1 R267.1 R269.1 R270.1 R271.2 R275.1 R278.1 R284.2 R293.1 R298.1 R300.1 R303.1 R305.2 R307.1 R311.1 R313.1 R315.1 R318.1 R320.2 R327.2 R334.2 R335.2 R336.2 R337.2 R338.1 R339.1 R340.1 R341.1 R342.1 R345.2 R346.2 R348.2 R349.2 R350.2 R352.2 R353.1 R354.1 R355.2 R358.2 R359.2 R361.2 R371.1 R372.1 R373.1 R374.1 R399.2 R402.2 R404.2 R425.2 R426.2 R433.2 R435.2 R437.1 R439.2 R440.2 R441.2 R448.1 R449.1 R450.1 R470.2 R472.1 R473.2 R474.2 R475.2 R476.2 SW3.9 SW4.2 SW4.3 SW4.4 T1.4 U2.15(GND) U3.1(GND) U4.8(GND) U4.11(EPAD) U5.49(GND) U6.49(GND) U7.13(GND) U8.A1(RG_A1) U8.A18(RG_A18) U8.B3(AVSS4) U8.B5(AVSS5) U8.B7(AVSS6) U8.B9(AVSS7) U8.B12(AVSS1) U8.B14(AVSS2) U8.B16(AVSS3) U8.C2(AVSS12) U8.C4(AVSS13) U8.C6(AVSS14) U8.C8(AVSS15) U8.C11(AVSS8) U8.C13(AVSS9) U8.C15(AVSS10) U8.C17(AVSS11) U8.D3(AVSS20) U8.D5(AVSS21) U8.D7(AVSS22) U8.D9(AVSS23) U8.D12(AVSS16) U8.D14(AVSS17) U8.D16(AVSS18) U8.D18(AVSS19) U8.E1(D\C\_\M\A\S\T\E\R\) U8.E4(AVSS28) U8.E6(AVSS_PLL) U8.E11(AVSS24) U8.E13(AVSS25) U8.E15(AVSS26) U8.E17(AVSS27) U8.F6(AVSS31) U8.F8(AVSS32) U8.F10(AVSS29) U8.F12(AVSS30) U8.G5(AVSS34) U8.G7(AVSS35) U8.G9(AVSS36) U8.G11(AVSS33) U8.H4(M\D\I\O\_\1\P\2\_\S\E\L\E\C\T\) U8.H6(AVSS39) U8.H8(AVSS40) U8.H10(AVSS37) U8.H12(AVSS38) U8.J5(VSS3) U8.J7(VSS4) U8.J9(VSS5) U8.J11(VSS1) U8.J13(VSS2) U8.K6(VSS8) U8.K8(VSS9) U8.K10(VSS6) U8.K12(VSS7) U8.L4(RG_L4) U8.L7(VSS12) U8.L9(VSS13) U8.L11(VSS10) U8.L13(VSS11) U8.M6(VSS16) U8.M8(VSS17) U8.M10(VSS14) U8.M12(VSS15) U8.N1(VSS_SRDS1) U8.N2(VSS_SRDS2) U8.N5(VSS20) U8.N7(VSS21) U8.N9(VSS22) U8.N11(VSS18) U8.N13(VSS19) U8.P3(VSS_SRDS5) U8.P6(VSS25) U8.P8(VSS26) U8.P10(VSS23) U8.P12(VSS24) U8.P17(VSS_SRDS3) U8.P18(VSS_SRDS4) U8.R1(VSS_SRDS6) U8.R2(VSS_SRDS8) U8.R4(VSS_SRDS9) U8.R6(VSS_SRDS10) U8.R7(VSS29) U8.R9(VSS30) U8.R11(VSS27) U8.R13(VSS28) U8.R14(VSS_SRDS7) U8.T3(VSS_SRDS14) U8.T5(VSS_SRDS15) U8.T7(VSS_SRDS16) U8.T9(VSS_SRDS17) U8.T11(VSS_SRDS11) U8.T13(VSS_SRDS12) U8.T15(VSS_SRDS13) U8.U1(VSS_SRDS18) U8.U5(VSS_SRDS22) U8.U9(VSS_SRDS23) U8.U11(VSS_SRDS19) U8.U16(VSS_SRDS20) U8.U18(VSS_SRDS21) U8.V5(VSS_SRDS26) U8.V9(VSS_SRDS27) U8.V11(VSS_SRDS24) U8.V16(VSS_SRDS25) U9.10(PGND1) U9.22(SGND) U9.25(PGND2) U10.4(GND) U11.8(AGND) U11.10(PGND) U11.17(PAD) U12.8(AGND) U12.10(PGND) U12.17(PAD) U13.1(E0) U13.2(E1) U13.3(E2) U13.4(VSS) U13.7(W\C\) U14.10(VSS) U15.8(GND) U15.15(E\) U16.C5(VSS1) U16.F7(VSS2) U16.K3(VSS3) U16.K8(VSS4) U19.25(GND) U20.33(VSS1) U20.52(VSS2) U21.A2(GND001) U21.A18(GND002) U21.A22(GND003) U21.AA6(SD_GND20) U21.AA7(SD_GND21) U21.AA8(SD_GND22) U21.AA9(SD_GND23) U21.AA10(SD_GND24) U21.AA11(SD_GND25) U21.AA12(SD_GND26) U21.AA13(SD_GND27) U21.AA14(SD_GND28) U21.AA15(SD_GND29) U21.AA16(SD_GND30) U21.AA17(SD_GND31) U21.AB1(GND108) U21.AB4(GND109) U21.AB6(SD_GND32) U21.AB8(SD_GND33) U21.AB10(SD_GND34) U21.AB12(SD_GND35) U21.AB15(SD_GND36) U21.AB17(SD_GND37) U21.AC2(GND110) U21.AC6(SD_GND38) U21.AC8(SD_GND39) U21.AC10(SD_GND40) U21.AC12(SD_GND41) U21.AC15(SD_GND42) U21.AC17(SD_GND43) U21.B1(GND004) U21.B3(GND005) U21.B7(GND006) U21.B10(GND007) U21.B13(GND008) U21.B16(GND009) U21.B18(GND010) U21.B20(GND011) U21.C1(USB_AGND01) U21.C2(USB_AGND02) U21.C4(GND012) U21.C19(GND013) U21.C22(GND014) U21.D3(USB_AGND03) U21.D18(GND015) U21.D20(GND016) U21.E1(USB_AGND04) U21.E2(USB_AGND05) U21.E6(GND017) U21.E9(GND018) U21.E12(GND019) U21.E15(GND020) U21.E19(GND021) U21.E22(GND022) U21.F3(USB_AGND06) U21.F17(GND023) U21.F20(GND024) U21.G1(USB_AGND07) U21.G2(USB_AGND08) U21.G6(GND025) U21.G9(USB_AGND09) U21.G10(GND026) U21.G11(GND027) U21.G12(GND028) U21.G13(GND029) U21.G14(GND030) U21.G15(GND031) U21.G17(TD1_ANODE) U21.G18(TD1_CATHODE) U21.G19(GND032) U21.G22(GND033) U21.H2(GND034) U21.H7(USB_AGND10) U21.H16(GND035) U21.H17(GND036) U21.H20(GND037) U21.J5(GND038) U21.J7(GND039) U21.J9(GND040) U21.J11(GND041) U21.J13(GND042) U21.J16(GND043) U21.J19(GND044) U21.J22(GND045) U21.K7(GND046) U21.K10(GND047) U21.K12(GND048) U21.K14(GND049) U21.K16(GND050) U21.K17(GND051) U21.K18(GND052) U21.K20(GND053) U21.L2(GND054) U21.L5(GND055) U21.L7(GND056) U21.L9(GND057) U21.L11(GND058) U21.L13(GND059) U21.L16(GND060) U21.L18(GND061) U21.L22(GND062) U21.M7(GND063) U21.M10(GND064) U21.M12(GND065) U21.M14(GND066) U21.M16(GND067) U21.M18(GND068) U21.M21(GND069) U21.N7(GND070) U21.N9(GND071) U21.N11(GND072) U21.N13(GND073) U21.N16(GND074) U21.N17(GND075) U21.N18(GND076) U21.P2(GND077) U21.P7(GND078) U21.P10(GND079) U21.P12(GND080) U21.P14(GND081) U21.P16(GND082) U21.P18(GND083) U21.P20(GND084) U21.P22(GND085) U21.R5(GND086) U21.R7(GND087) U21.R9(GND088) U21.R11(GND089) U21.R13(GND090) U21.R16(GND091) U21.R17(GND092) U21.T7(GND093) U21.T10(GND094) U21.T14(GND095) U21.T16(GND096) U21.T22(GND097) U21.U2(GND098) U21.U5(GND099) U21.U8(GND100) U21.U9(GND101) U21.U11(SD_GND01) U21.U12(SD_GND02) U21.U13(SD_GND03) U21.U15(SD_GND04) U21.U16(GND102) U21.U23(GND103) U21.V4(GND104) U21.V6(SD_GND05) U21.V7(SD_GND06) U21.V9(SD_GND07) U21.V16(SD_GND08) U21.W6(SD_GND09) U21.W8(SD_GND10) U21.W10(SD_GND11) U21.W12(SD_GND12) U21.W15(SD_GND13) U21.W17(GND105) U21.Y2(GND106) U21.Y5(GND107) U21.Y6(SD_GND14) U21.Y8(SD_GND15) U21.Y10(SD_GND16) U21.Y12(SD_GND17) U21.Y15(SD_GND18) U21.Y17(SD_GND19) U22.1(SYNC) U22.8(PGND1) U22.9(PGND2) U22.10(PGND3) U22.11(GND1) U22.12(GND2) U22.13(GND3) U22.14(GND4) U22.25(GND5) U22.26(GND6) U22.27(GND7) U22.28(GND8) U22.29(GND9) U23.3(GND) U24.3(GND) U25.1(1\O\E\) U25.4(GND1) U25.10(GND2) U25.15(GND3) U25.21(GND4) U25.24(2\O\E\) U25.28(GND5) U25.34(GND6) U25.39(GND7) U25.45(GND8) U26.8(AGND) U26.10(PGND) U26.17(PAD) U27.3(GND) U28.1(SYNC) U28.8(PGND1) U28.9(PGND2) U28.10(PGND3) U28.11(GND1) U28.12(GND2) U28.13(GND3) U28.14(GND4) U28.25(GND5) U28.26(GND6) U28.27(GND7) U28.28(GND8) U28.29(GND9) U29.1(SYNC) U29.8(PGND1) U29.9(PGND2) U29.10(PGND3) U29.11(GND1) U29.12(GND2) U29.13(GND3) U29.14(GND4) U29.25(GND5) U29.26(GND6) U29.27(GND7) U29.28(GND8) U29.29(GND9) U30.9(GND) U31.9(GND) U32.8(GND) U32.15(E\) U33.8(GND) U33.15(E\) U34.A2(VSSQ1) U34.A8(VSSQ2) U34.A9(VSS1) U34.C8(VSS2) U34.D1(VSSQ3) U34.D9(VSSQ4) U34.E1(VSS3) U34.E9(VSS4) U34.G1(VSS5) U34.H9(VSS6) U34.K1(VSS7) U34.K9(VSS8) U34.N1(VSS9) U35.A2(VSSQ1) U35.A8(VSSQ2) U35.A9(VSS1) U35.C8(VSS2) U35.D1(VSSQ3) U35.D9(VSSQ4) U35.E1(VSS3) U35.E9(VSS4) U35.G1(VSS5) U35.H9(VSS6) U35.K1(VSS7) U35.K9(VSS8) U35.N1(VSS9) U36.A2(VSSQ1) U36.A8(VSSQ2) U36.A9(VSS1) U36.C8(VSS2) U36.D1(VSSQ3) U36.D9(VSSQ4) U36.E1(VSS3) U36.E9(VSS4) U36.G1(VSS5) U36.H9(VSS6) U36.K1(VSS7) U36.K9(VSS8) U36.N1(VSS9) U37.A2(VSSQ1) U37.A8(VSSQ2) U37.A9(VSS1) U37.C8(VSS2) U37.D1(VSSQ3) U37.D9(VSSQ4) U37.E1(VSS3) U37.E9(VSS4) U37.G1(VSS5) U37.H9(VSS6) U37.K1(VSS7) U37.K9(VSS8) U37.N1(VSS9) U38.4(STBY) U38.5(ICTEST1) U38.14(SGND1) U38.15(SGND2) U38.32(SGND3) U38.47(ICTEST2) U38.48(SGND4) U38.57(EPGND) U39.C4(VSSQ5) U39.E7(VSS1) U39.G5(VSS2) U39.H10(VSS3) U39.K8(VSS4) U39.N2(VSSQ1) U39.N5(VSSQ2) U39.P4(VSSQ3) U39.P6(VSSQ4) U40.2(A2) U41.4(GND) U42.7(GND) U43.16(GND) U44.6(GND1) U44.7(GND2) U44.8(O\E\) U45.1(SYNC) U45.8(PGND1) U45.9(PGND2) U45.10(PGND3) U45.11(GND1) U45.12(GND2) U45.13(GND3) U45.14(GND4) U45.25(GND5) U45.26(GND6) U45.27(GND7) U45.28(GND8) U45.29(GND9) U47.7(GND) U48.2(ADDR) U48.8(GND) U49.1(SYNC) U49.8(PGND1) U49.9(PGND2) U49.10(PGND3) U49.11(GND1) U49.12(GND2) U49.13(GND3) U49.14(GND4) U49.25(GND5) U49.26(GND6) U49.27(GND7) U49.28(GND8) U49.29(GND9) Y1.2(GND1) Y1.4(GND2) Y2.2(GND1) Y2.4(GND2) Y3.2 Y3.4 Y5.2 Y5.4
GND_EARTH: C167.2 C168.2 C169.2 C171.2 C172.2 J2.S1(SGND1) J2.S2(SGND2) J3.S1(GND1) J3.S2(GND2) J4.21 J4.22 J5.21 J5.22 J24.S1(GND1) J24.S2(GND2) P1.9 P1.10
GND_SIGNAL: C2.2 C21.1 C170.2 C173.2 C174.2 C175.2 C178.1 C181.2 C183.2 C184.2 R2.1 R3.2 R4.2 R13.2 R186.1 R190.2 R191.2 R192.2 T1.3 T2.2 U1.13(SYNC) U1.19(SENSE-) U1.26(VNEG1) U1.27(VNEG2) U1.33(EP_GND)
VBAT_OPT1: R84.1 U10.3(VBACKUP)
2.5G_CMP_N: J3.15(CMS-) U8.D8(CM_N)
2.5G_CMP_P: J3.14(CMS+) U8.E8(CM_P)
2.5G_MDI0_N: J3.9(TRD1-) J24.9(TRD1-) U8.A2(A_N)
2.5G_MDI0_P: J3.8(TRD1+) J24.8(TRD1+) U8.B2(A_P)
2.5G_MDI1_N: J3.3(TRD2-) J24.3(TRD2-) U8.A4(B_N)
2.5G_MDI1_P: J3.2(TRD2+) J24.2(TRD2+) U8.B4(B_P)
2.5G_MDI2_N: J3.5(TRD3-) J24.5(TRD3-) U8.A6(C_N)
2.5G_MDI2_P: J3.4(TRD3+) J24.4(TRD3+) U8.B6(C_P)
2.5G_MDI3_N: J3.11(TRD4-) J24.11(TRD4-) U8.A8(D_N)
2.5G_MDI3_P: J3.10(TRD4+) J24.10(TRD4+) U8.B8(D_P)
12: D1.A D22.C R455.1 R456.1
34: D3.A D20.C R454.1 R457.1
56: D2.A D21.C R453.1 R458.1
78: D4.A D19.C R452.1 R459.1
A23: U20.1(A23) U27.4(Y)
A24: U20.56(A24) U24.4(Y)
A25: U20.55(A25) U23.4(Y)
ADP_12V: C59.1 C77.1 C79.1 C80.1 Q5.4(D2) Q6.3(S) R100.1 R102.1 R447.1 U47.8(VBUS)
AQR105_FLASH: C198.1 C218.2 C238.2 C240.2 C245.2 C246.2 C500.1 C501.1 C502.1 C503.1 C559.1 C560.1 C561.1 C562.1 C565.1 C566.1 C567.1 C568.1 C575.1 C576.1 C577.1 C578.1 C596.1 J7.6 L10.1 R75.2 R76.2 R212.2 R216.2 R222.1 R392.1 R393.1 U8.E3(VDD_FLASH) U8.J3(VDD_IO1) U8.K4(VDD_IO3) U8.K16(VDD_IO2) U8.L16(VDD_IO4) U34.B1(VPP1) U34.M9(VPP2) U35.B1(VPP1) U35.M9(VPP2) U36.B1(VPP1) U36.M9(VPP2) U37.B1(VPP1) U37.M9(VPP2) U38.28(LDO3) U41.3(W\P\) U41.7(H\O\L\D\) U41.8(VCC)
AQR105_VA12: C49.1 C54.1 C63.1 C216.2 C219.2 C220.2 C223.2 C224.2 C339.1 R83.2 R200.1 R209.1 R227.2 R229.2 R280.1 U8.D4(VA12_1) U8.D6(VA12_2) U8.E5(VA12_3) U8.E7(VA12_4) U8.E9(VA12_5) U12.3(OUT1) U12.4(OUT2) U21.P5(TVDD)
AQR105_VA22: C34.1 C35.1 C58.1 C62.1 C76.1 C194.2 C195.2 C196.2 C197.2 C207.2 C209.2 C210.2 C211.2 C263.2 C271.2 L12.2 R85.1 U8.A3(VA22_1) U8.A5(VA22_2) U8.A7(VA22_3) U8.A9(VA22_4) U8.C3(VA22_5) U8.C5(VA22_6) U8.C7(VA22_7) U8.C9(VA22_8) U8.P4(V22_SRDS1) U8.R3(V22_SRDS2) U11.3(OUT1) U11.4(OUT2)
AQR105_VDD: C47.1 C55.1 C61.1 C68.1 C69.1 C70.1 C225.2 C226.2 C227.2 C231.2 C232.2 C239.2 C242.2 C243.2 C244.2 C248.2 C249.2 C252.2 C253.2 C254.2 C255.2 C256.2 C257.2 C258.2 C259.2 C260.2 C261.2 C262.2 C264.2 C265.2 C266.2 C267.2 C268.2 C270.2 C272.2 L8.2 L16.2 L17.2 R82.1 U8.J6(VDD2) U8.J8(VDD3) U8.J10(VDD29) U8.J12(VDD1) U8.K5(VDD6) U8.K7(VDD7) U8.K9(VDD8) U8.K11(VDD4) U8.K13(VDD5) U8.L6(VDD11) U8.L8(VDD12) U8.L10(VDD9) U8.L12(VDD10) U8.M7(VDD15) U8.M9(VDD16) U8.M11(VDD13) U8.M13(VDD14) U8.N6(VDD19) U8.N8(VDD20) U8.N10(VDD17) U8.N12(VDD18) U8.P5(VDD23) U8.P7(VDD24) U8.P9(VDD25) U8.P11(VDD21) U8.P13(VDD22) U8.R8(VDD28) U8.R10(VDD26) U8.R12(VDD27) U9.9(VON)
AQR_INT_N: R228.2 R280.2 U21.T3(IRQ3/GPIO1_23)
AQR_LED_GRN: C602.1 D14.3(CATHODE2) R26.1 U8.K1(LED0)
AQR_LED_YEL: C601.1 D14.4(CATHODE1) R24.1 U8.L1(LED1)
AQR_SPI_CS: R216.1 U8.G2(C\E\) U41.1(C\S\)
AQR_SPI_SCLK: U8.G1(SCLK) U41.6(SCLK)
AQR_SPI_SDI: U8.F1(SIN) U41.2(SO/SIO1)
AQR_SPI_SDO: U8.F2(SOUT) U41.5(SI/SIO0)
COP_CKSTP_OUT_N: J13.15 Q9.3(COLLECTOR) R366.1
COP_HRST: J13.13 Q24.2(EMITTER) R365.1
COP_SRST: J13.11 Q8.2(EMITTER) R364.1
COP_TCK: J13.7 R362.1 U44.3(A3)
COP_TDI: J13.3 R360.1 U44.1(A1)
COP_TDO: J13.1 U44.2(A2)
COP_TMS: J13.9 R363.1 U44.4(A4)
COP_TRST: J13.4 Q10.2(EMITTER) R369.1
CPU_RST_REQ: Q1.2(EMITTER) R17.2 U21.F6(R\E\S\E\T\_\R\E\Q\)
D1_MVREF: C546.1 C547.1 C548.1 C549.1 C564.1 U34.J1(VREFCA) U35.J1(VREFCA) U36.J1(VREFCA) U37.J1(VREFCA) U38.31(REFOUT)
DCDC1_3V3: C95.1 C106.1 C107.1 C428.1 C439.1 C440.1 C443.1 C455.1 L19.2 P3.2(3.3V_1) P3.24(+3.3VAUX) P3.39(RESERVED4) P3.41(RESERVED5) P3.52(3.3V_2) R35.1 R149.1 R220.1 R224.1 U28.22(BIAS)
DCDC2_3V3: C6.1 C66.1 C84.2 C97.1 C108.1 C109.1 C118.1 C127.1 C138.1 C139.1 C157.1 C163.2 C182.2 C283.1 C284.1 C285.1 C286.1 C292.1 C293.1 C294.1 C295.1 C332.1 C346.1 C351.1 C370.1 C386.2 C469.1 C477.1 C524.1 C525.1 C534.1 C544.1 C545.1 C550.1 C551.1 C556.1 C557.1 C558.1 C563.1 C570.1 C579.1 C580.1 C581.1 C582.1 C583.1 C592.1 C598.1 C609.1 C611.1 C646.1 D15.A(ANODE) D16.A(ANODE) D17.A(ANODE) J19.3 L20.2 L25.1 L26.2 L27.2 Q7.1(S2) Q23.3(DRAIN) R8.1 R15.2 R23.2 R86.1 R118.1 R119.2 R120.1 R125.2 R152.1 R167.2 R172.2 R198.2 R221.1 R226.1 R246.1 R259.1 R260.1 R264.1 R265.1 R291.1 R360.2 R362.2 R363.2 R364.2 R365.2 R366.2 R369.2 R370.1 R395.1 R400.1 R401.1 R451.1 R466.2 U2.16(VCC) U3.4(VCC) U10.8(VCC) U11.12(IN1) U11.14(IN2) U12.9(S\H\D\N\) U12.12(IN1) U12.14(IN2) U13.8(VCC) U14.2(VCC) U15.16(VCC) U20.43(VCC) U21.M8(DVDD1) U21.N8(DVDD2) U22.22(BIAS) U26.12(IN1) U26.14(IN2) U29.22(BIAS) U32.16(VCC) U33.16(VCC) U38.7(PVIN1_1) U38.10(PVIN1_2) U38.12(PVIN1_3) U38.17(VLDOIN1) U38.20(PVIN4) U38.23(PVIN2_1) U38.24(PVIN2_2) U38.27(VLDOIN23) U38.34(PVIN3_1) U38.37(PVIN3_2) U38.40(VLDOIN45) U38.50(VIN) U38.55(VCCI2C) U39.E6(VCC3) U39.F5(VCC2) U39.J10(VCC1) U39.K9(VCC4) U42.6(VCC) U43.1(CLK_EN) U43.9(VDD1) U43.10(VDD2) U43.15(VDD3) U44.16(VCCA) U47.6(VCC) U48.1(VCCI)
DCDC2_3V3_PG: R167.1 U29.23(PG) U38.56(EN)
DCDC_1V0: C341.1 C345.1 C360.1 C362.1 C363.1 C364.1 C367.1 C368.1 C369.1 C372.1 C373.1 C374.1 C376.1 C378.1 C379.1 C380.1 C383.1 C387.1 C388.1 C393.1 C394.1 C395.1 C396.1 C397.1 C398.1 C399.1 C400.1 C410.1 C412.1 C413.1 C414.1 C415.1 C416.1 C418.1 C420.1 C441.1 L28.2 R326.2 R444.2 U21.J10(VDD01) U21.J12(VDD02) U21.J14(VDD03) U21.K9(VDD04) U21.K11(VDD05) U21.K13(VDD06) U21.L10(VDD07) U21.L12(VDD08) U21.L14(VDD09) U21.M9(VDD10) U21.M11(VDD11) U21.M13(VDD12) U21.N10(VDD13) U21.N12(VDD14) U21.N14(VDD15) U21.P9(VDD16) U21.P11(VDD17) U21.P13(VDD18) U21.R10(VDD19) U21.R12(VDD20) U21.R14(VDD21) U21.T9(VDD22)
DCDC_1V0_SUP: C87.1 C90.1 C93.1 C94.1 L18.2 R127.1 R326.1 R445.2 U42.8(VBUS)
DCDC_5V0: C10.1 C15.1 L11.2 U4.1(INA) U7.11(VOUT)
DDR4_A0: R386.2 U21.AC22(D1_MA00) U34.L3(A0) U35.L3(A0) U36.L3(A0) U37.L3(A0)
DDR4_A1: R176.2 U21.Y19(D1_MA01) U34.L7(A1) U35.L7(A1) U36.L7(A1) U37.L7(A1)
DDR4_A2: R389.2 U21.V21(D1_MA02) U34.M3(A2) U35.M3(A2) U36.M3(A2) U37.M3(A2)
DDR4_A3: R182.2 U21.U17(D1_MA03) U34.K7(A3) U35.K7(A3) U36.K7(A3) U37.K7(A3)
DDR4_A4: R178.2 U21.AA20(D1_MA04) U34.K3(A4) U35.K3(A4) U36.K3(A4) U37.K3(A4)
DDR4_A5: R174.2 U21.W20(D1_MA05) U34.L8(A5) U35.L8(A5) U36.L8(A5) U37.L8(A5)
DDR4_A6: R384.2 U21.V19(D1_MA06) U34.L2(A6) U35.L2(A6) U36.L2(A6) U37.L2(A6)
DDR4_A7: R175.2 U21.U20(D1_MA07) U34.M8(A7) U35.M8(A7) U36.M8(A7) U37.M8(A7)
DDR4_A8: R385.2 U21.T20(D1_MA08) U34.M2(A8) U35.M2(A8) U36.M2(A8) U37.M2(A8)
DDR4_A9: R391.2 U21.T21(D1_MA09) U34.M7(A9) U35.M7(A9) U36.M7(A9) U37.M7(A9)
DDR4_A10: R180.2 U21.AA19(D1_MA10) U34.J3(A10/AP) U35.J3(A10/AP) U36.J3(A10/AP) U37.J3(A10/AP)
DDR4_A11: R388.2 U21.U21(D1_MA11) U34.N2(A11) U35.N2(A11) U36.N2(A11) U37.N2(A11)
DDR4_A12: R171.2 U21.U19(D1_MA12) U34.J7(A12/B\C\) U35.J7(A12/B\C\) U36.J7(A12/B\C\) U37.J7(A12/B\C\)
DDR4_A13: R177.2 U21.Y21(D1_MA13) U34.N8(A13) U35.N8(A13) U36.N8(A13) U37.N8(A13)
DDR4_A14/WE: R378.2 U21.AB19(D\1\_\M\W\E\) U34.H2(W\E\/A14) U35.H2(W\E\/A14) U36.H2(W\E\/A14) U37.H2(W\E\/A14)
DDR4_ACT_N: R382.2 U21.R19(D1_MA15) U34.H3(A\C\T\) U35.H3(A\C\T\) U36.H3(A\C\T\) U37.H3(A\C\T\)
DDR4_BA0: R383.2 U21.AC21(D1_MBA0) U34.K2(BA0) U35.K2(BA0) U36.K2(BA0) U37.K2(BA0)
DDR4_BA1: R173.2 U21.AA21(D1_MBA1) U34.K8(BA1) U35.K8(BA1) U36.K8(BA1) U37.K8(BA1)
DDR4_BG0: R380.2 U21.R18(D1_MBA2) U34.J2(BG0) U35.J2(BG0) U36.J2(BG0) U37.J2(BG0)
DDR4_BG1: R170.2 U21.T18(D1_MA14) U34.J8(BG1) U35.J8(BG1) U36.J8(BG1) U37.J8(BG1)
DDR4_CAS: R183.2 U21.W18(D\1\_\M\C\A\S\) U34.H7(C\A\S\/A15) U35.H7(C\A\S\/A15) U36.H7(C\A\S\/A15) U37.H7(C\A\S\/A15)
DDR4_CS0: R376.2 U21.AB21(D\1\_\M\C\S\0\) U34.G7(C\S\) U35.G7(C\S\) U36.G7(C\S\) U37.G7(C\S\)
DDR4_CS1: R168.2 U21.AA18(D\1\_\M\C\S\1\) U34.G8(C1/C\S\1\) U35.G8(C1/C\S\1\) U36.G8(C1/C\S\1\) U37.G8(C1/C\S\1\)
DDR4_DM0: U21.A21(D1_MDM0) U37.A7(NF/D\M\/D\B\I\/TDQS_T)
DDR4_DM1: U21.E21(D1_MDM1) U36.A7(NF/D\M\/D\B\I\/TDQS_T)
DDR4_DM2: U21.H22(D1_MDM2) U35.A7(NF/D\M\/D\B\I\/TDQS_T)
DDR4_DM3: U21.L20(D1_MDM3) U34.A7(NF/D\M\/D\B\I\/TDQS_T)
DDR4_DQ0: U21.A19(D1_MDQ00) U37.C2(DQ0)
DDR4_DQ1: U21.C20(D1_MDQ01) U37.B7(DQ1)
DDR4_DQ2: U21.C23(D1_MDQ02) U37.D3(DQ2)
DDR4_DQ3: U21.D23(D1_MDQ03) U37.D7(DQ3)
DDR4_DQ4: U21.B19(D1_MDQ04) U37.D2(DQ4/NC)
DDR4_DQ5: U21.A20(D1_MDQ05) U37.D8(DQ5/NC)
DDR4_DQ6: U21.B23(D1_MDQ06) U37.E3(DQ6/NC)
DDR4_DQ7: U21.D22(D1_MDQ07) U37.E7(DQ7/NC)
DDR4_DQ8: U21.C21(D1_MDQ08) U36.C2(DQ0)
DDR4_DQ9: U21.E20(D1_MDQ09) U36.B7(DQ1)
DDR4_DQ10: U21.H21(D1_MDQ10) U36.D3(DQ2)
DDR4_DQ11: U21.J21(D1_MDQ11) U36.D7(DQ3)
DDR4_DQ12: U21.D19(D1_MDQ12) U36.D2(DQ4/NC)
DDR4_DQ13: U21.D21(D1_MDQ13) U36.D8(DQ5/NC)
DDR4_DQ14: U21.G20(D1_MDQ14) U36.E3(DQ6/NC)
DDR4_DQ15: U21.J20(D1_MDQ15) U36.E7(DQ7/NC)
DDR4_DQ16: U21.F22(D1_MDQ16) U35.C2(DQ0)
DDR4_DQ17: U21.G23(D1_MDQ17) U35.B7(DQ1)
DDR4_DQ18: U21.K23(D1_MDQ18) U35.D3(DQ2)
DDR4_DQ19: U21.M22(D1_MDQ19) U35.D7(DQ3)
DDR4_DQ20: U21.E23(D1_MDQ20) U35.D2(DQ4/NC)
DDR4_DQ21: U21.F23(D1_MDQ21) U35.D8(DQ5/NC)
DDR4_DQ22: U21.K22(D1_MDQ22) U35.E3(DQ6/NC)
DDR4_DQ23: U21.L23(D1_MDQ23) U35.E7(DQ7/NC)
DDR4_DQ24: U21.K21(D1_MDQ24) U34.C2(DQ0)
DDR4_DQ25: U21.L21(D1_MDQ25) U34.B7(DQ1)
DDR4_DQ26: U21.N21(D1_MDQ26) U34.D3(DQ2)
DDR4_DQ27: U21.P21(D1_MDQ27) U34.D7(DQ3)
DDR4_DQ28: U21.K19(D1_MDQ28) U34.D2(DQ4/NC)
DDR4_DQ29: U21.L19(D1_MDQ29) U34.D8(DQ5/NC)
DDR4_DQ30: U21.N20(D1_MDQ30) U34.E3(DQ6/NC)
DDR4_DQ31: U21.N19(D1_MDQ31) U34.E7(DQ7/NC)
DDR4_DQS0: U21.B22(D1_MDQS0) U37.C3(DQS_T)
DDR4_DQS0_N: U21.B21(D\1\_\M\D\Q\S\0\) U37.B3(DQS_C)
DDR4_DQS1: U21.G21(D1_MDQS1) U36.C3(DQS_T)
DDR4_DQS1_N: U21.F21(D\1\_\M\D\Q\S\1\) U36.B3(DQS_C)
DDR4_DQS2: U21.J23(D1_MDQS2) U35.C3(DQS_T)
DDR4_DQS2_N: U21.H23(D\1\_\M\D\Q\S\2\) U35.B3(DQS_C)
DDR4_DQS3: U21.M19(D1_MDQS3) U34.C3(DQS_T)
DDR4_DQS3_N: U21.M20(D\1\_\M\D\Q\S\3\) U34.B3(DQS_C)
DDR4_MCK0: R379.2 U21.W22(D1_MCK0) U34.F7(CK_T) U35.F7(CK_T) U36.F7(CK_T) U37.F7(CK_T)
DDR4_MCK0_N: R381.1 U21.W23(D\1\_\M\C\K\0\) U34.F8(CK_C) U35.F8(CK_C) U36.F8(CK_C) U37.F8(CK_C)
DDR4_MCKE0: R181.2 U21.R20(D1_MCKE0) U34.G3(CKE) U35.G3(CKE) U36.G3(CKE) U37.G3(CKE)
DDR4_MCKE1: R377.2 U21.U18(D1_MCKE1) U34.G2(C0/CKE1) U35.G2(C0/CKE1) U36.G2(C0/CKE1) U37.G2(C0/CKE1)
DDR4_ODT0: R375.2 U21.W19(D1_MODT0) U34.F3(ODT) U35.F3(ODT) U36.F3(ODT) U37.F3(ODT)
DDR4_ODT1: R166.2 U21.AC20(D1_MODT1) U34.F2(C2/ODT1) U35.F2(C2/ODT1) U36.F2(C2/ODT1) U37.F2(C2/ODT1)
DDR4_PAR: R387.2 U21.U22(D1_MAPAR_OUT) U34.N3(PAR) U35.N3(PAR) U36.N3(PAR) U37.N3(PAR)
DDR4_PAR_ERR: R390.2 U21.W21(D\1\_\M\A\P\A\R\_\E\R\R\) U34.L9(A\L\E\R\T\) U35.L9(A\L\E\R\T\) U36.L9(A\L\E\R\T\) U37.L9(A\L\E\R\T\)
DDR4_RAS: R169.2 U21.AC18(D\1\_\M\R\A\S\) U34.H8(R\A\S\/A16) U35.H8(R\A\S\/A16) U36.H8(R\A\S\/A16) U37.H8(R\A\S\/A16)
DDR4_VDD: C110.1 C111.1 C112.1 C114.1 C115.1 C117.1 C133.1 C136.1 C143.1 C145.1 C430.1 C432.1 C433.1 C434.1 C435.1 C436.1 C437.1 C438.1 C442.1 C445.1 C446.1 C447.1 C453.1 C454.1 C459.1 C460.1 C468.1 C470.1 C471.1 C472.1 C473.1 C475.1 C476.1 C479.1 C482.1 C483.1 C484.1 C488.1 C489.1 C490.1 C491.1 C492.1 C493.1 C494.1 C495.1 C496.1 C497.1 C498.1 C499.1 C504.1 C505.1 C506.1 C507.1 C508.1 C509.1 C510.1 C511.1 C512.1 C513.1 C514.1 C515.1 C516.1 C517.1 C518.1 C519.1 C520.1 C521.1 C522.1 C523.1 C526.1 C527.1 C528.1 C529.1 C530.1 C531.1 C532.1 C533.1 C535.1 C536.1 C537.1 C538.1 C539.1 C540.1 C541.1 C542.1 C543.1 C552.1 C553.1 C554.1 C555.1 C569.1 C571.1 C572.1 C573.1 C574.1 C584.2 C585.2 C586.2 C587.2 C588.2 C589.2 C591.2 L21.2 R343.1 R390.1 U21.AB18(G1VDD19) U21.AB20(G1VDD20) U21.AB22(G1VDD21) U21.J15(G1VDD01) U21.K15(G1VDD02) U21.L15(G1VDD03) U21.M15(G1VDD04) U21.N15(G1VDD05) U21.P15(G1VDD06) U21.P19(G1VDD07) U21.R15(G1VDD08) U21.R21(G1VDD09) U21.T15(G1VDD10) U21.T17(G1VDD11) U21.T19(G1VDD12) U21.V18(G1VDD13) U21.V20(G1VDD14) U21.V22(G1VDD15) U21.Y18(G1VDD16) U21.Y20(G1VDD17) U21.Y22(G1VDD18) U34.A1(VDD1) U34.B2(VDDQ1) U34.B8(VDDQ2) U34.C1(VDDQ3) U34.C7(VDD2) U34.C9(VDDQ4) U34.E2(VDDQ5) U34.E8(VDDQ6) U34.F1(VDD3) U34.F9(VDD4) U34.H1(VDD5) U34.J9(VDD6) U34.M1(VDD7) U34.N9(VDD8) U35.A1(VDD1) U35.B2(VDDQ1) U35.B8(VDDQ2) U35.C1(VDDQ3) U35.C7(VDD2) U35.C9(VDDQ4) U35.E2(VDDQ5) U35.E8(VDDQ6) U35.F1(VDD3) U35.F9(VDD4) U35.H1(VDD5) U35.J9(VDD6) U35.M1(VDD7) U35.N9(VDD8) U36.A1(VDD1) U36.B2(VDDQ1) U36.B8(VDDQ2) U36.C1(VDDQ3) U36.C7(VDD2) U36.C9(VDDQ4) U36.E2(VDDQ5) U36.E8(VDDQ6) U36.F1(VDD3) U36.F9(VDD4) U36.H1(VDD5) U36.J9(VDD6) U36.M1(VDD7) U36.N9(VDD8) U37.A1(VDD1) U37.B2(VDDQ1) U37.B8(VDDQ2) U37.C1(VDDQ3) U37.C7(VDD2) U37.C9(VDDQ4) U37.E2(VDDQ5) U37.E8(VDDQ6) U37.F1(VDD3) U37.F9(VDD4) U37.H1(VDD5) U37.J9(VDD6) U37.M1(VDD7) U37.N9(VDD8) U38.30(REFIN) U38.38(FB3)
DDR4_VTT: C119.1 C120.1 C121.1 C123.1 C128.1 C131.1 C134.1 C135.1 C137.1 C144.1 C146.1 C148.1 C150.1 C151.1 C156.1 C158.1 C159.1 C160.1 C161.1 C162.1 C164.1 C165.1 C166.1 C485.1 C486.1 C487.1 C584.1 C585.1 C586.1 C587.1 C588.1 C589.1 C591.1 C593.1 C594.1 C595.1 C599.1 C600.1 C605.1 C606.1 L23.2 R166.1 R168.1 R169.1 R170.1 R171.1 R173.1 R174.1 R175.1 R176.1 R177.1 R178.1 R180.1 R181.1 R182.1 R183.1 R375.1 R376.1 R377.1 R378.1 R380.1 R382.1 R383.1 R384.1 R385.1 R386.1 R387.1 R388.1 R389.1 R391.1 U38.19(FB4)
EC1_AVDD10: C204.2 C205.2 C215.2 R66.2 U5.4(AVDD10_1) U5.9(AVDD10_2) U5.47(AVDD10_3)
EC1_CLK_125M: C42.1 R50.2 R404.1 U21.W4(EC1_GTX_CLK125/GPIO3_17)
EC1_DVDD10: C222.2 R74.2 U5.22(DVDD10)
EC1_DVDD_3V3: C236.2 C247.1 R34.1 R57.2 R70.2 R221.2 U5.30(DVDD33)
EC1_DVDDRG: C229.1 C237.2 R217.2 U5.29(DVDD_RG)
EC1_LED0/PHYAD0: C24.1 C608.1 D12.4(CATHODE1) J4.17 R70.1 U5.35(LED0/PHYAD0)
EC1_LED1/CFG_LDO0: R31.1 R63.2 R396.1 U5.36(LED1/CFG_LDO0)
EC1_LED2/CFG_LDO1: R57.1 U5.37(LED2/CFG_LDO1)
EC1_MDIN0: J4.10 U5.3(MDIN0)
EC1_MDIN1: J4.5 U5.6(MDIN1)
EC1_MDIN2: J4.2 U5.8(MDIN2)
EC1_MDIN3: J4.9 U5.11(MDIN3)
EC1_MDIP0: J4.11 U5.2(MDIP0)
EC1_MDIP1: J4.4 U5.5(MDIP1)
EC1_MDIP2: J4.3 U5.7(MDIP2)
EC1_MDIP3: J4.8 U5.10(MDIP3)
EC1_PHY_INT_N: R281.2 U5.34(I\N\T\/P\M\E\) U21.Y3(IRQ2)
EC1_RXC: C45.1 R65.2 U21.T1(EC1_RX_CLK/GPIO3_23)
EC1_RXC/PHYAD1: R65.1 R73.2 U5.28(RXC/PHYAD1)
EC1_RXCTL: R62.2 U21.W1(EC1_RX_DV/GPIO3_22)
EC1_RXCTL/PHYAD2: R62.1 R72.2 U5.27(RXCTL/PHYAD2)
